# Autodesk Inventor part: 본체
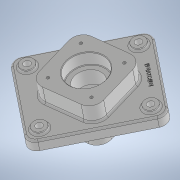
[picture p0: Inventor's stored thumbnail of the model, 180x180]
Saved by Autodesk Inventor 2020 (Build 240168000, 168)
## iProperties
Created: 2021-07
Part Number: 본체
Material: 일반
Document SubType Name: Modeling
Designer: Owner
Density: 1 g/cm^3
Appearance: 기본값
Mass: 807.977 g
Surface Area: 961.758 cm^2
Volume: 807.977 cm^3
Author: Owner
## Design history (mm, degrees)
sketch "스케치1"
  geometry: L1 (90, 75)-(-90, 75); L2 (-90, 75)-(-90, -75); L3 (-90, -75)-(90, -75); L4 (90, -75)-(90, 75); L5 (90, 75)-(-90, -75); L6 (-90, 75)-(90, -75); 1 further point
  constraints: 12 end point, 2 midpoint, 2 parallel, 1 horizontal, 1 perpendicular
  dimensions: "d0" = 180 distance of L3.end L2.end; "d1" = 150 distance of L2.end L1.end
extrude "돌출1" new body sketch "스케치1" distance "d2" = 18; taper "d3" = 0 deg
fillet "모깎기1" dims "d4" = 15
sketch "스케치2"
  geometry: L1 (70.711, 0)-(0, -70.711); L2 (0, -70.711)-(-70.711, 0); L3 (-70.711, 0)-(0, 70.711); L4 (0, 70.711)-(70.711, 0); L5 (70.711, 0)-(-70.711, 0); L6 (0, -70.711)-(0, 70.711); 4 further points
  constraints: 12 end point, 4 midpoint, 2 parallel, 1 coincident, 1 horizontal alignment, 1 perpendicular, 1 vertical alignment
  dimensions: "d5" = 100 distance of L1.end L2.end
extrude "돌출7" join sketch "스케치2" distance "d76" = 23; taper "d77" = 0 deg
sketch "스케치12"
  geometry: L1 (0, 70.711)-(70.711, 0) reference; L2 (70.711, 0)-(0, -70.711) reference; L3 (0, -70.711)-(-70.711, 0) reference; L4 (-70.711, 0)-(0, 70.711) reference; 1 further point
extrude "돌출8" join sketch "스케치12" distance "d78" = 29; taper "d79" = 0 deg
fillet "모깎기8" dims "d80" = 20
node "작업 평면2"
sketch "스케치17"
  geometry: L1 (-14.142, 56.569)-(-56.569, 14.142) reference; L2 (-56.569, -14.142)-(-14.142, -56.569) reference; L3 (14.142, -56.569)-(56.569, -14.142) reference; L4 (56.569, 14.142)-(14.142, 56.569) reference; A1 r 20 centre (0, 42.426) between (14.142, 56.569) and (-14.142, 56.569) reference; A2 r 20 centre (-42.426, 0) between (-56.569, 14.142) and (-56.569, -14.142) reference; A3 r 20 centre (0, -42.426) between (-14.142, -56.569) and (14.142, -56.569) reference; A4 r 20 centre (42.426, 0) between (56.569, -14.142) and (56.569, 14.142) reference; 1 further point
hole "구멍7" sketch "스케치17" at (0, 0) diameter "d91" = 45; stored, may be unused: countersink angle "d95" = 90 deg, drill point angle "d97" = 118 deg; dims "d92" = 10, "d93" = 62, "d94" = 22, "d96" = 13
sketch "스케치18"
  geometry: C1 r 22.5 at (0, 0) reference; 2 further points
  constraints: 1 coincident
hole "구멍8" sketch "스케치18" at (0, 0) diameter "d98" = 45; stored, may be unused: countersink angle "d102" = 90 deg, drill point angle "d104" = 118 deg; dims "d99" = 10, "d100" = 62, "d101" = 22, "d103" = 13
sketch "스케치19"
  geometry: 2 further points
  constraints: 1 horizontal alignment
  dimensions: "d105" = 48 distance of point (0, 0) point (-48, 0)
hole "구멍9" sketch "스케치19" at (-48, 0) diameter "d106" = 4.917; stored, may be unused: countersink angle "d110" = 90 deg, drill point angle "d112" = 118 deg; dims "d107" = 10, "d108" = 62, "d109" = 22, "d111" = 13
sketch "스케치20"
  geometry: 2 further points
  constraints: 1 horizontal alignment
  dimensions: "d116" = 48 distance of point (0, 0) point (-48, 0)
hole "구멍10" sketch "스케치20" at (-48, 0) diameter "d117" = 4.917; stored, may be unused: countersink angle "d121" = 90 deg, drill point angle "d123" = 118 deg; dims "d118" = 10, "d119" = 62, "d120" = 22, "d122" = 13
sketch "스케치21"
  geometry: L1 (-90, -60)-(-90, 60) reference; 2 further points
  constraints: 1 horizontal alignment, 1 other
  dimensions: "d129" = 15 distance from line of L1 point (-75, 0)
feature "엠보싱2" sketch "스케치21" dims "d0" = 180, "d1" = 150, "d130" = 0.5, "d131" = 0
fillet "모깎기9" dims "d132" = 3
sketch "스케치22"
  geometry: L1 (70, -55)-(-70, -55); L2 (-70, -55)-(-70, 55); L3 (-70, 55)-(70, 55); L4 (70, 55)-(70, -55); L5 (70, -55)-(-70, 55); L6 (-70, -55)-(70, 55); C1 r 22.5 at (0, 0) reference; C2 r 11 at (-70, -55); C3 r 11 at (-70, 55); C4 r 11 at (70, 55); C5 r 11 at (70, -55); 5 further points
  constraints: 12 end point, 8 coincident, 4 centre point, 2 midpoint, 2 parallel, 1 horizontal, 1 perpendicular
  dimensions: "d133" = 140 distance of L2.end L3.end; "d134" = 110 distance of L1.end L2.end; "d135" = 22 diameter of C2; "d136" = 22 diameter of C3; "d137" = 22 diameter of C4; "d138" = 22 diameter of C5
extrude "돌출10" join sketch "스케치22" distance "d139" = 5; taper "d140" = 0 deg
extrude "돌출11" join sketch "스케치22" distance "d141" = 5; taper "d142" = 0 deg
extrude "돌출12" join sketch "스케치22" distance "d143" = 5; taper "d144" = 0 deg
extrude "돌출13" join sketch "스케치22" distance "d145" = 5; taper "d146" = 0 deg
sketch "스케치23"
  geometry: C1 r 11 at (0, 0) reference; C2 r 11 at (-140, 0) reference; C3 r 11 at (-140, -110) reference; C4 r 11 at (0, -110) reference; 5 further points
  constraints: 4 coincident
hole "구멍11" sketch "스케치23" at (0, 0), (-140, 0), (-140, -110), (0, -110) diameter "d147" = 11; stored, may be unused: countersink angle "d151" = 90 deg, drill point angle "d153" = 118 deg; dims "d148" = 10, "d149" = 62, "d150" = 22, "d152" = 13
fillet "모깎기10" dims "d154" = 3
chamfer "모따기2" distance "d155" = 1; stored, may be unused: second distance "d156" = 2, angle "d157" = 45 deg
fillet "모깎기11" dims "d158" = 1
fillet "모깎기12" dims "d159" = 3
node "솔리드1"
pattern_circular "원형 패턴3" dims angle "d114" = 360 deg
pattern_circular "원형 패턴4" dims angle "d125" = 360 deg
node "투영된 루프5"
node "투영된 루프6"
feature "A9D066F2-1C7D-4E18-AEED-F7BC21143FA4" dims "d91" = 45, "d92" = 10, "d93" = 62, "d94" = 22, "d95" = 90 deg, "d96" = 13, "d97" = 118 deg
